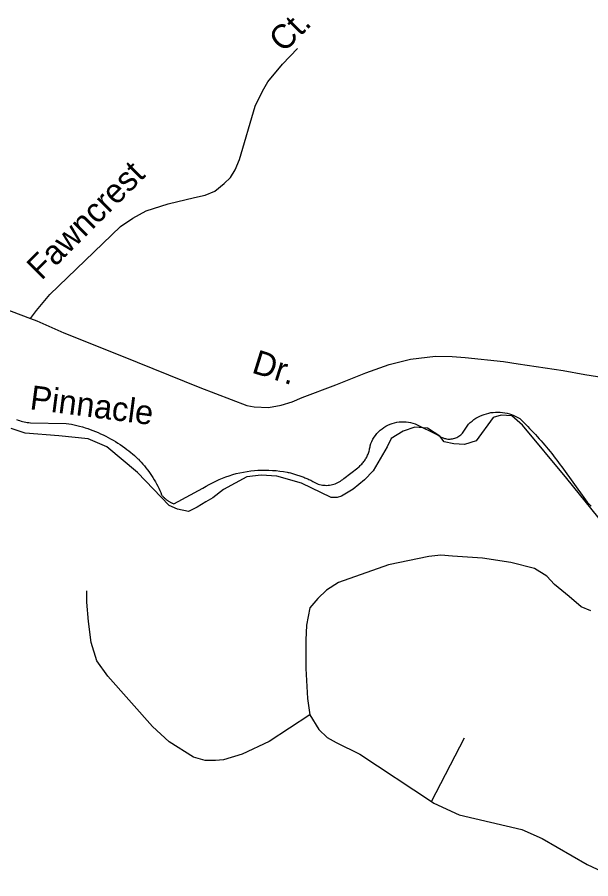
# Model space of a CAD drawing. Extents: x 884530 to 1028605, y 526725 to 653634.
# Drawn here: x 968262 to 969824, y 560062 to 562406 of the extents above; entities that cross this region are included whole.
import ezdxf

# ---------------------------------------------------------------- set-up
doc = ezdxf.new("R2010")
doc.units = 0
for name, color, linetype in [('Exist Boundary Political City Limit New', 7, 'Continuous'), ('Exist Road Non-System Type 51', 7, 'Continuous'), ('Exist Road Non-System Type 51 Label', 7, 'Continuous'), ('Exist Road Secondary Type 51 Attributed', 7, 'Continuous'), ('Exist Road Secondary Type 51 Label', 7, 'Continuous'), ('Map Preparation Boundary City Limit Buffer Line', 7, 'Continuous')]:
    doc.layers.add(name, color=color, linetype=linetype)

msp = doc.modelspace()

# ---------------------------------------------------------------- linework, layer by layer
at = {"layer": 'Exist Boundary Political City Limit New'}
for points in [[(969301.6, 561304.8), (969307.9, 561305.4), (969314.2, 561305.5), (969320.6, 561305.2), (969326.9, 561304.4), (969333.1, 561303.2), (969339.2, 561301.7), (969345.2, 561299.7), (969408.4, 561268.5), (969410.9, 561267), (969413.6, 561265.2), (969416.3, 561263.7), (969419.1, 561262.3), (969422.1, 561261.1), (969425.1, 561260.1), (969428.1, 561259.3), (969431.2, 561258.7), (969434.4, 561258.3), (969437.6, 561258.1), (969440.8, 561258.2), (969443.9, 561258.4), (969447, 561258.9), (969450.1, 561259.6), (969453.1, 561260.4), (969456.1, 561261.5), (969459, 561262.8), (969461.8, 561264.2), (969464.5, 561265.8), (969467.1, 561267.6), (969469.5, 561269.6), (969471.8, 561271.8), (969474, 561274.1), (969476, 561276.5), (969490.8, 561298.9), (969495.4, 561303.2), (969500.3, 561307.3), (969505.4, 561311.1), (969510.6, 561314.6), (969516.1, 561317.8), (969521.7, 561320.6), (969527.5, 561323.2), (969533.4, 561325.4), (969539.5, 561327.2), (969545.6, 561328.8), (969551.8, 561330), (969558.1, 561330.8), (969564.1, 561331.3), (969570.7, 561331.4), (969577, 561331.2), (969583.3, 561330.6), (969589.6, 561329.7), (969595.8, 561328.4), (969601.9, 561326.8), (969607.9, 561324.9), (969613.8, 561322.6), (969619.5, 561319.9), (969625.1, 561317), (969630.4, 561313.7), (969635.8, 561308.4), (969641.2, 561303.1), (969646.6, 561297.8), (969651.9, 561292.4), (969657.2, 561286.9), (969662.5, 561281.4), (969667.7, 561275.9), (969672.9, 561270.4), (969678, 561264.8), (969683.1, 561259.1), (969688.1, 561253.4), (969693.1, 561247.8), (969698.1, 561242), (969702.9, 561236.2), (969707.8, 561230.4), (969712.6, 561224.5), (969717.4, 561218.6), (969722.1, 561212.6), (969726.8, 561206.6), (969731.4, 561200.6), (969736, 561194.6), (969740.6, 561188.5), (969745.1, 561182.4), (969749.5, 561176.2), (969805.1, 561099), (969809.2, 561092.5), (969813.8, 561086.4), (969818.9, 561080.7), (969824.4, 561075.4)], [(968260, 561311.3), (968264.1, 561309.8), (968268.2, 561308.4)], [(968268.2, 561308.4), (968272.3, 561307.2), (968276.5, 561306.1), (968280.8, 561305.1), (968285, 561304.2), (968289.2, 561303.5), (968293.6, 561302.9), (968297.9, 561302.5), (968394.8, 561300.9), (968402.3, 561300), (968409.8, 561298.5), (968417.2, 561296.9), (968424.6, 561295.1), (968431.9, 561293.2), (968439.2, 561291.1), (968442, 561290.3), (968446.5, 561288.9), (968453.8, 561286.6), (968460.9, 561284.1), (968468.1, 561281.4), (968475.1, 561278.6), (968482.1, 561275.7), (968489.1, 561272.6), (968495.9, 561269.4), (968502.8, 561266), (968509.5, 561262.5), (968516.2, 561258.9), (968522.8, 561255.1), (968529.3, 561251.2), (968535.8, 561247.2), (968542.1, 561243), (968548.4, 561238.7), (968554.6, 561234.2), (968560.7, 561229.7), (968565.9, 561226.1), (968571.1, 561222), (968576.1, 561217.8), (968581, 561213.4), (968585.8, 561209), (968590.5, 561204.4), (968591.8, 561203.1), (968595.1, 561199.8), (968599.6, 561195), (968604, 561190.1), (968608.2, 561185.1), (968612.4, 561180.1), (968616.5, 561174.9), (968620.4, 561169.6), (968624.2, 561164.2), (968627.9, 561158.8), (968631.5, 561153.3), (968634.9, 561147.7), (968638.2, 561142), (968641.4, 561136.2), (968644.4, 561130.4), (968647.3, 561124.6), (968650.1, 561118.6), (968652.7, 561112.6), (968654.8, 561106.6), (968655.9, 561105.2), (968657, 561103.9), (968658.2, 561102.6), (968659.4, 561101.3), (968660.6, 561100.1), (968661.9, 561098.9), (968663.1, 561097.7), (968664.4, 561096.5), (968665.8, 561095.4), (968667.1, 561094.2), (968668.5, 561093.2), (968669.9, 561092.1), (968671.3, 561091.1), (968672.8, 561090.1), (968674.2, 561089.2), (968675.8, 561088.2), (968677.2, 561087.4), (968678.8, 561086.5), (968680.3, 561085.7), (968681.9, 561084.9), (968683.4, 561084.1), (968685.1, 561083.4), (968686.7, 561082.8), (968688.3, 561082.1), (968767.5, 561124.2), (968776, 561129.8), (968784.6, 561134.8), (968793.4, 561139.4), (968802.4, 561143.8), (968811.4, 561147.9), (968820.6, 561151.8), (968829.9, 561155.2), (968839.4, 561158.5), (968848.9, 561161.4), (968858.5, 561164.1), (968868.2, 561166.4), (968877.9, 561168.4), (968887.8, 561170.1), (968897.6, 561171.4), (968907.6, 561172.5), (968917.5, 561173.2)], [(968917.5, 561173.2), (968927.4, 561173.7), (968933.6, 561173.8), (968937.4, 561173.8), (968947.3, 561173.6), (968957.2, 561173.1), (968967.2, 561172.3), (968977.1, 561171.2), (968986.9, 561169.8), (968996.8, 561168), (968999.9, 561167.5), (969002.8, 561166.8), (969005.6, 561166.1), (969008.5, 561165.4), (969011.4, 561164.6), (969014.2, 561163.8), (969017.1, 561163), (969019.9, 561162.1), (969022.7, 561161.2), (969025.5, 561160.3), (969028.3, 561159.4), (969031.1, 561158.4), (969033.9, 561157.4), (969036.7, 561156.4), (969039.4, 561155.3), (969042.2, 561154.2), (969044.9, 561153.1), (969047.7, 561152), (969050.4, 561150.8), (969053.1, 561149.6), (969055.8, 561148.4), (969058.5, 561147.1), (969061.2, 561145.9), (969063.8, 561144.6), (969067.1, 561142.4), (969070.6, 561140.5), (969074.1, 561138.8), (969077.8, 561137.2), (969081.4, 561135.8), (969085.2, 561134.7), (969089.1, 561133.8), (969092.9, 561133.1), (969096.9, 561132.6), (969100.8, 561132.3), (969104.8, 561132.2), (969108.7, 561132.4), (969112.6, 561132.8), (969116.5, 561133.4), (969120.4, 561134.2), (969124.2, 561135.3), (969127.9, 561136.6), (969131.6, 561138.1), (969135.2, 561139.8), (969138.7, 561141.6), (969142.1, 561143.7), (969145.3, 561145.9), (969148.4, 561148.4), (969151.4, 561151), (969188.9, 561179.8), (969191.2, 561182), (969193.5, 561183.9), (969195.7, 561185.8), (969197.8, 561187.9), (969199.9, 561190), (969201.9, 561192.2), (969203.8, 561194.4), (969205.6, 561196.8), (969207.4, 561199.1), (969209.1, 561201.6), (969210.6, 561204.1), (969212.1, 561206.6), (969213.6, 561209.2), (969214.9, 561211.8), (969216.1, 561214.5), (969217.2, 561217.2), (969218.3, 561220), (969219.2, 561222.8), (969220.1, 561225.6), (969220.9, 561228.5), (969221.5, 561231.4), (969222.1, 561234.2), (969222.5, 561237.2), (969222.9, 561240.1), (969225.1, 561246.1), (969227.6, 561251.9), (969230.6, 561257.5), (969233.9, 561262.9), (969237.5, 561268.1), (969241.5, 561273.1), (969245.8, 561277.7), (969250.4, 561282), (969255.3, 561286), (969260.4, 561289.7), (969265.8, 561293), (969271.4, 561295.9), (969277.2, 561298.5), (969283.1, 561300.7), (969289.2, 561302.5), (969295.4, 561303.9), (969301.6, 561304.8)]]:
    msp.add_lwpolyline(points, dxfattribs=at)
at = {"layer": 'Exist Road Non-System Type 51'}
msp.add_line((969389.7, 560272), (969479.8, 560445.2), dxfattribs=at)
for points in [[(968297.7, 561586), (968314.5, 561607.9), (968351.1, 561651.4), (968543.4, 561836.8), (968576.3, 561859.1), (968613.3, 561879.4), (968672.6, 561897.9), (968745, 561915), (968773.7, 561921.9), (968800.4, 561932.9), (968825.5, 561953.8), (968842.3, 561970.2), (968855.6, 561991.1), (968866.9, 562018.5), (968909.4, 562163.8), (968929.5, 562204.9), (968944.7, 562229.9), (968983.8, 562278.2), (969025, 562321.1)], [(968146.5, 561643.2), (968297.7, 561586)], [(968297.7, 561586), (968315.5, 561579.8), (968388.8, 561546.9), (968546.1, 561484.2), (968759.3, 561398.6), (968887.1, 561349.9), (968906.7, 561345.5), (968945.7, 561343.7), (968980.7, 561350.2), (969010.5, 561359.1), (969037.8, 561371.2), (969129.5, 561406), (969210.7, 561438.6), (969274.3, 561461.3), (969333, 561475.3), (969401.2, 561483.6), (969445.8, 561483.2), (969481.7, 561480.4), (969585.6, 561468.8), (969626, 561463.3), (969748.7, 561444.4), (969807, 561433.8), (969842, 561428.8), (969860.2, 561423.8)], [(969824, 560791), (969797.5, 560802.1), (969764.5, 560829.6), (969725.1, 560862.9), (969703.9, 560884.8), (969670.8, 560906.4), (969605.6, 560922.6), (969528.6, 560934.3), (969447, 560939.9), (969415.1, 560942.1), (969382.9, 560938.9), (969272.6, 560915.8), (969137.1, 560867.8), (969104.3, 560847), (969080.7, 560824.7), (969059.1, 560798.8), (969049.5, 560751.4), (969048, 560710.7), (969048, 560634.4), (969052.5, 560552.2), (969058.4, 560507.8), (969058.5, 560507.6)], [(969058.5, 560507.6), (968948.3, 560435.1), (968874, 560400.9), (968823.2, 560385.5), (968802.1, 560383.8), (968773.5, 560384), (968742.1, 560392.9), (968676, 560434.8), (968630.4, 560476.5), (968508.8, 560613.3), (968478.4, 560655.1), (968463.1, 560704.5), (968455.7, 560761.5), (968451.8, 560814.6), (968451.8, 560845.1)], [(969058.5, 560507.6), (969083.2, 560467.8), (969105.9, 560446.5), (969130.1, 560432.3), (969194.5, 560400.9), (969389.7, 560272)], [(969389.7, 560272), (969396.6, 560267.3), (969464.9, 560236.2), (969635.5, 560195.9), (969691.4, 560171.1), (969813.9, 560100.6), (969870.2, 560074.7), (969903.2, 560061.9)]]:
    msp.add_lwpolyline(points, dxfattribs=at)
at = {"layer": 'Exist Road Secondary Type 51 Attributed'}
for points in [[(969877.1, 561003.6), (969758.2, 561151), (969637.7, 561295.7), (969608.8, 561321.1), (969580, 561322.8), (969558.2, 561316.7), (969511.9, 561253.3), (969479.6, 561243.7), (969450.7, 561245.4), (969424.4, 561250.4), (969413, 561265.9), (969378.9, 561287.6), (969344.8, 561290.7), (969312.7, 561279.4), (969280.4, 561259.4), (969269.4, 561237.4)], [(969269.4, 561237.4), (969231, 561171.8), (969207.8, 561147.5), (969176.8, 561121.6), (969144.7, 561103), (969133.3, 561098.9), (969116.8, 561099.5), (969036.3, 561137.8), (968969, 561157.5), (968926.5, 561159.9), (968887.3, 561155.8), (968823.7, 561121.1), (968794.7, 561098.4), (968775.1, 561087), (968752.3, 561072.5), (968728.4, 561061.4), (968698.7, 561067.6), (968676, 561077.2), (968589.6, 561167.2), (968505.6, 561237.1), (968455, 561259), (968375.5, 561266.9), (968283.8, 561274.3), (968245.4, 561286.9)]]:
    msp.add_lwpolyline(points, dxfattribs=at)
at = {"layer": 'Map Preparation Boundary City Limit Buffer Line'}
for points in [[(969301.6, 561304.8), (969307.9, 561305.4), (969314.2, 561305.5), (969320.6, 561305.2), (969326.9, 561304.4), (969333.1, 561303.2), (969339.2, 561301.7), (969345.2, 561299.7), (969408.4, 561268.5), (969410.9, 561267), (969413.6, 561265.2), (969416.3, 561263.7), (969419.1, 561262.3), (969422.1, 561261.1), (969425.1, 561260.1), (969428.1, 561259.3), (969431.2, 561258.7), (969434.4, 561258.3), (969437.6, 561258.1), (969440.8, 561258.2), (969443.9, 561258.4), (969447, 561258.9), (969450.1, 561259.6), (969453.1, 561260.4), (969456.1, 561261.5), (969459, 561262.8), (969461.8, 561264.2), (969464.5, 561265.8), (969467.1, 561267.6), (969469.5, 561269.6), (969471.8, 561271.8), (969474, 561274.1), (969476, 561276.5), (969490.8, 561298.9), (969495.4, 561303.2), (969500.3, 561307.3), (969505.4, 561311.1), (969510.6, 561314.6), (969516.1, 561317.8), (969521.7, 561320.6), (969527.5, 561323.2), (969533.4, 561325.4), (969539.5, 561327.2), (969545.6, 561328.8), (969551.8, 561330), (969558.1, 561330.8), (969564.1, 561331.3), (969570.7, 561331.4), (969577, 561331.2), (969583.3, 561330.6), (969589.6, 561329.7), (969595.8, 561328.4), (969601.9, 561326.8), (969607.9, 561324.9), (969613.8, 561322.6), (969619.5, 561319.9), (969625.1, 561317), (969630.4, 561313.7), (969635.8, 561308.4), (969641.2, 561303.1), (969646.6, 561297.8), (969651.9, 561292.4), (969657.2, 561286.9), (969662.5, 561281.4), (969667.7, 561275.9), (969672.9, 561270.4), (969678, 561264.8), (969683.1, 561259.1), (969688.1, 561253.4), (969693.1, 561247.8), (969698.1, 561242), (969702.9, 561236.2), (969707.8, 561230.4), (969712.6, 561224.5), (969717.4, 561218.6), (969722.1, 561212.6), (969726.8, 561206.6), (969731.4, 561200.6), (969736, 561194.6), (969740.6, 561188.5), (969745.1, 561182.4), (969749.5, 561176.2), (969805.1, 561099), (969809.2, 561092.5), (969813.8, 561086.4), (969818.9, 561080.7), (969824.4, 561075.4)], [(968260, 561311.3), (968264.1, 561309.8), (968268.2, 561308.4)], [(968268.2, 561308.4), (968272.3, 561307.2), (968276.5, 561306.1), (968280.8, 561305.1), (968285, 561304.2), (968289.2, 561303.5), (968293.6, 561302.9), (968297.9, 561302.5), (968394.8, 561300.9), (968402.3, 561300), (968409.8, 561298.5), (968417.2, 561296.9), (968424.6, 561295.1), (968431.9, 561293.2), (968439.2, 561291.1), (968442, 561290.3), (968446.5, 561288.9), (968453.8, 561286.6), (968460.9, 561284.1), (968468.1, 561281.4), (968475.1, 561278.6), (968482.1, 561275.7), (968489.1, 561272.6), (968495.9, 561269.4), (968502.8, 561266), (968509.5, 561262.5), (968516.2, 561258.9), (968522.8, 561255.1), (968529.3, 561251.2), (968535.8, 561247.2), (968542.1, 561243), (968548.4, 561238.7), (968554.6, 561234.2), (968560.7, 561229.7), (968565.9, 561226.1), (968571.1, 561222), (968576.1, 561217.8), (968581, 561213.4), (968585.8, 561209), (968590.5, 561204.4), (968591.8, 561203.1), (968595.1, 561199.8), (968599.6, 561195), (968604, 561190.1), (968608.2, 561185.1), (968612.4, 561180.1), (968616.5, 561174.9), (968620.4, 561169.6), (968624.2, 561164.2), (968627.9, 561158.8), (968631.5, 561153.3), (968634.9, 561147.7), (968638.2, 561142), (968641.4, 561136.2), (968644.4, 561130.4), (968647.3, 561124.6), (968650.1, 561118.6), (968652.7, 561112.6), (968654.8, 561106.6), (968655.9, 561105.2), (968657, 561103.9), (968658.2, 561102.6), (968659.4, 561101.3), (968660.6, 561100.1), (968661.9, 561098.9), (968663.1, 561097.7), (968664.4, 561096.5), (968665.8, 561095.4), (968667.1, 561094.2), (968668.5, 561093.2), (968669.9, 561092.1), (968671.3, 561091.1), (968672.8, 561090.1), (968674.2, 561089.2), (968675.8, 561088.2), (968677.2, 561087.4), (968678.8, 561086.5), (968680.3, 561085.7), (968681.9, 561084.9), (968683.4, 561084.1), (968685.1, 561083.4), (968686.7, 561082.8), (968688.3, 561082.1), (968767.5, 561124.2), (968776, 561129.8), (968784.6, 561134.8), (968793.4, 561139.4), (968802.4, 561143.8), (968811.4, 561147.9), (968820.6, 561151.8), (968829.9, 561155.2), (968839.4, 561158.5), (968848.9, 561161.4), (968858.5, 561164.1), (968868.2, 561166.4), (968877.9, 561168.4), (968887.8, 561170.1), (968897.6, 561171.4), (968907.6, 561172.5), (968917.5, 561173.2)], [(968917.5, 561173.2), (968927.4, 561173.7), (968933.6, 561173.8), (968937.4, 561173.8), (968947.3, 561173.6), (968957.2, 561173.1), (968967.2, 561172.3), (968977.1, 561171.2), (968986.9, 561169.8), (968996.8, 561168), (968999.9, 561167.5), (969002.8, 561166.8), (969005.6, 561166.1), (969008.5, 561165.4), (969011.4, 561164.6), (969014.2, 561163.8), (969017.1, 561163), (969019.9, 561162.1), (969022.7, 561161.2), (969025.5, 561160.3), (969028.3, 561159.4), (969031.1, 561158.4), (969033.9, 561157.4), (969036.7, 561156.4), (969039.4, 561155.3), (969042.2, 561154.2), (969044.9, 561153.1), (969047.7, 561152), (969050.4, 561150.8), (969053.1, 561149.6), (969055.8, 561148.4), (969058.5, 561147.1), (969061.2, 561145.9), (969063.8, 561144.6), (969067.1, 561142.4), (969070.6, 561140.5), (969074.1, 561138.8), (969077.8, 561137.2), (969081.4, 561135.8), (969085.2, 561134.7), (969089.1, 561133.8), (969092.9, 561133.1), (969096.9, 561132.6), (969100.8, 561132.3), (969104.8, 561132.2), (969108.7, 561132.4), (969112.6, 561132.8), (969116.5, 561133.4), (969120.4, 561134.2), (969124.2, 561135.3), (969127.9, 561136.6), (969131.6, 561138.1), (969135.2, 561139.8), (969138.7, 561141.6), (969142.1, 561143.7), (969145.3, 561145.9), (969148.4, 561148.4), (969151.4, 561151), (969188.9, 561179.8), (969191.2, 561182), (969193.5, 561183.9), (969195.7, 561185.8), (969197.8, 561187.9), (969199.9, 561190), (969201.9, 561192.2), (969203.8, 561194.4), (969205.6, 561196.8), (969207.4, 561199.1), (969209.1, 561201.6), (969210.6, 561204.1), (969212.1, 561206.6), (969213.6, 561209.2), (969214.9, 561211.8), (969216.1, 561214.5), (969217.2, 561217.2), (969218.3, 561220), (969219.2, 561222.8), (969220.1, 561225.6), (969220.9, 561228.5), (969221.5, 561231.4), (969222.1, 561234.2), (969222.5, 561237.2), (969222.9, 561240.1), (969225.1, 561246.1), (969227.6, 561251.9), (969230.6, 561257.5), (969233.9, 561262.9), (969237.5, 561268.1), (969241.5, 561273.1), (969245.8, 561277.7), (969250.4, 561282), (969255.3, 561286), (969260.4, 561289.7), (969265.8, 561293), (969271.4, 561295.9), (969277.2, 561298.5), (969283.1, 561300.7), (969289.2, 561302.5), (969295.4, 561303.9), (969301.6, 561304.8)]]:
    msp.add_lwpolyline(points, dxfattribs=at)

# ---------------------------------------------------------------- texts
at = {"layer": 'Exist Road Non-System Type 51 Label'}
for s, rotation, p in [('Ct.', 45.0241, (968987.3, 562307.3)), ('Fawncrest', 45.0241, (968327.7, 561688)), ('Dr.', 342.6321, (968897.6, 561439.6))]:
    msp.add_text(s, height=65.62, rotation=rotation, dxfattribs=at).set_placement(p)
at = {"layer": 'Exist Road Secondary Type 51 Label'}
msp.add_text('Pinnacle', height=65.62, rotation=352.5612, dxfattribs=at).set_placement((968294.2, 561339.7))

doc.saveas('drawing.dxf')
